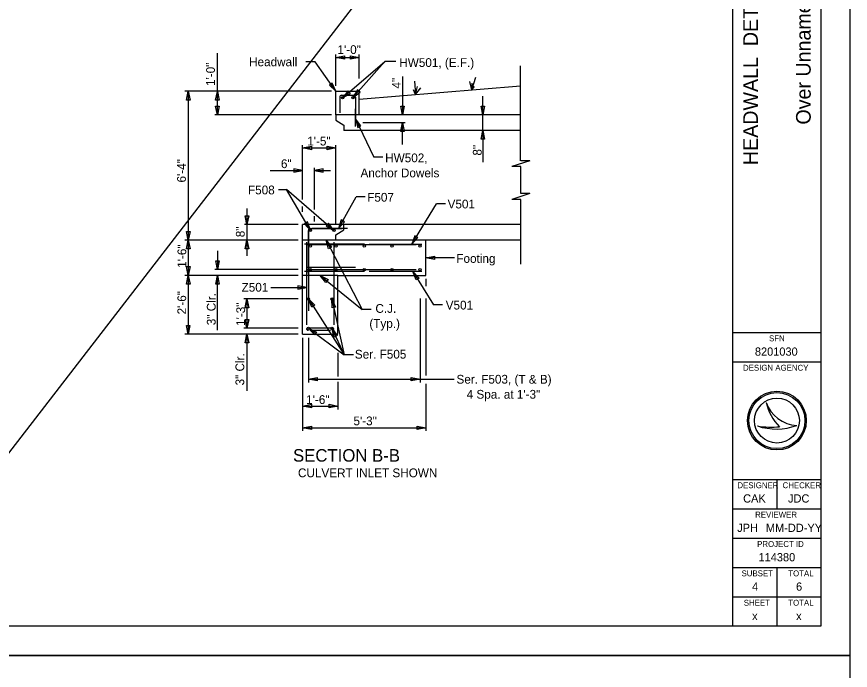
# Model space of a CAD drawing. Extents: x -1609 to 1184, y -412 to 394.
# Drawn here: x -1077.4 to -1041.89, y -99.47 to -71.66 of the extents above; entities that cross this region are included whole.
import ezdxf

# ---------------------------------------------------------------- set-up
doc = ezdxf.new("R2010")
doc.units = 0
for name, color, linetype in [('SH_Border', 7, 'Continuous'), ('SH_Cut_Line', 7, 'Continuous'), ('SH_Data', 7, 'Continuous'), ('ST_Details', 7, 'Continuous'), ('ST_Text', 7, 'Continuous'), ('XS_P_Finished_Grade', 7, 'Continuous')]:
    doc.layers.add(name, color=color, linetype=linetype)

msp = doc.modelspace()

# ---------------------------------------------------------------- linework, layer by layer
at = {"layer": 'SH_Border'}
for p, q in [((-1046.891, -97.594), (-1046.891, -45.094)), ((-1046.891, -85.094), (-1043.141, -85.094)), ((-1046.891, -86.344), (-1043.141, -86.344)), ((-1046.891, -91.344), (-1043.141, -91.344)), ((-1045.016, -91.344), (-1045.016, -92.594)), ((-1046.891, -92.594), (-1043.141, -92.594)), ((-1046.891, -93.844), (-1043.141, -93.844)), ((-1046.891, -95.094), (-1043.141, -95.094)), ((-1045.016, -95.094), (-1045.016, -96.344)), ((-1046.891, -96.344), (-1043.141, -96.344)), ((-1045.016, -96.344), (-1045.016, -97.594))]:
    msp.add_line(p, q, dxfattribs=at)
msp.add_lwpolyline([(-1123.141, -45.094), (-1043.141, -45.094), (-1043.141, -97.594), (-1123.141, -97.594)], close=True, dxfattribs=at)
at = {"layer": 'SH_Cut_Line'}
for points in [[(-1126.891, -98.844), (-1041.891, -98.844), (-1041.891, -43.844), (-1126.891, -43.844)], [(-1126.891, -153.844), (-1041.891, -153.844), (-1041.891, -98.844), (-1126.891, -98.844)]]:
    msp.add_lwpolyline(points, close=True, dxfattribs=at)
at = {"layer": 'SH_Data'}
for p, q in [((-1045.472, -88.07), (-1045.472, -88.07)), ((-1045.848, -89.07), (-1045.848, -89.07)), ((-1045.016, -88.844), (-1045.016, -88.844)), ((-1044.173, -89.048), (-1044.173, -89.048))]:
    msp.add_line(p, q, dxfattribs=at)
for radius in [1.25, 1.192, 1.192, 0.956]:
    msp.add_circle((-1045.016, -88.844), radius, dxfattribs=at)
for centre, radius, start, end in [((-1044.101, -87.6), 1.45, 198.9257, 198.9319), ((-1043.524, -87.669), 1.989, 191.6379, 191.6421), ((-1044.101, -87.6), 1.45, 198.9319, 267.1657), ((-1043.524, -87.669), 1.989, 191.6421, 226.0947), ((-1045.042, -86.669), 2.533, 251.4576, 290.0832), ((-1045.271, -85.958), 3.165, 259.4964, 259.4995), ((-1045.042, -86.669), 2.533, 251.4527, 251.4576), ((-1045.271, -85.958), 3.165, 259.4995, 276.6672)]:
    msp.add_arc(centre, radius, start, end, dxfattribs=at)
at = {"layer": 'ST_Details'}
for p, q in [((-1055.931, -77.783), (-1055.931, -73.749)), ((-1060.449, -74.396), (-1060.406, -74.965)), ((-1058.015, -74.766), (-1058.099, -74.408)), ((-1058.015, -74.766), (-1057.843, -74.23)), ((-1058.004, -74.486), (-1058.015, -74.766)), ((-1063.802, -75.832), (-1063.802, -74.832)), ((-1063.802, -74.832), (-1062.802, -74.832)), ((-1062.802, -75.832), (-1062.802, -74.832)), ((-1060.406, -74.965), (-1060.497, -74.771)), ((-1060.406, -74.965), (-1060.326, -74.62)), ((-1060.406, -74.965), (-1060.185, -74.681)), ((-1058.015, -74.766), (-1057.903, -74.622)), ((-1063.635, -75.079), (-1063.635, -75.748)), ((-1063.555, -74.999), (-1063.048, -74.999)), ((-1062.968, -75.079), (-1062.968, -76.165)), ((-1062.968, -76.332), (-1062.968, -75.578)), ((-1063.802, -75.832), (-1063.802, -75.836)), ((-1055.931, -75.832), (-1063.802, -75.832)), ((-1063.802, -75.832), (-1063.802, -76.054)), ((-1063.802, -76.054), (-1063.469, -76.276)), ((-1063.469, -76.276), (-1063.469, -76.498)), ((-1055.931, -76.499), (-1063.469, -76.499)), ((-1055.539, -77.783), (-1056.313, -78.028)), ((-1055.926, -78.028), (-1056.313, -78.028)), ((-1055.539, -77.783), (-1055.926, -77.783)), ((-1055.926, -79.186), (-1055.926, -78.028)), ((-1055.535, -79.186), (-1056.308, -79.431)), ((-1055.921, -79.431), (-1056.308, -79.431)), ((-1055.926, -82.19), (-1055.926, -79.431)), ((-1055.535, -79.186), (-1055.921, -79.186)), ((-1063.469, -80.499), (-1065.218, -80.499)), ((-1065.218, -81.499), (-1065.218, -80.499)), ((-1063.469, -80.721), (-1063.469, -80.499)), ((-1055.931, -80.499), (-1063.469, -80.499)), ((-1064.969, -80.745), (-1064.969, -84.169)), ((-1064.969, -82.582), (-1064.969, -80.749)), ((-1064.886, -80.665), (-1063.552, -80.665)), ((-1063.301, -80.665), (-1064.82, -80.665)), ((-1063.802, -80.943), (-1063.469, -80.721)), ((-1063.802, -81.165), (-1063.802, -80.943)), ((-1065.218, -85.165), (-1065.218, -81.165)), ((-1063.802, -81.165), (-1065.218, -81.165)), ((-1059.968, -81.165), (-1063.802, -81.165)), ((-1055.931, -81.165), (-1063.802, -81.165)), ((-1059.968, -82.665), (-1059.968, -81.165)), ((-1062.585, -81.332), (-1065.135, -81.332)), ((-1065.052, -81.344), (-1060.384, -81.344)), ((-1063.885, -81.333), (-1063.885, -83.836)), ((-1062.385, -81.332), (-1060.135, -81.332)), ((-1062.966, -82.332), (-1065.052, -82.332)), ((-1063.718, -82.665), (-1065.218, -82.665)), ((-1065.052, -82.419), (-1060.384, -82.419)), ((-1063.718, -82.665), (-1059.968, -82.665)), ((-1063.718, -85.165), (-1063.718, -82.665)), ((-1060.135, -82.499), (-1062.385, -82.499)), ((-1065.218, -85.165), (-1063.718, -85.165)), ((-1063.965, -84.915), (-1064.903, -84.915))]:
    msp.add_line(p, q, dxfattribs=at)
for points in [[(-1065.052, -81.249), (-1065.052, -84.769)], [(-1063.885, -81.249), (-1063.885, -83.583)], [(-1065.052, -81.344), (-1063.052, -81.344)], [(-1062.585, -82.499), (-1065.135, -82.499)], [(-1063.885, -83.453), (-1063.885, -84.769)], [(-1064.903, -84.999), (-1064.032, -84.999)]]:
    msp.add_lwpolyline(points, dxfattribs=at)
for centre in [(-1063.517, -75.105), (-1063.077, -75.097), (-1064.886, -80.749), (-1063.885, -80.749), (-1064.886, -81.415), (-1063.802, -81.415), (-1062.593, -81.415), (-1061.406, -81.415), (-1060.218, -81.415), (-1064.886, -82.416), (-1063.802, -82.416), (-1062.593, -82.415), (-1061.406, -82.415), (-1060.218, -82.415), (-1064.968, -83.666), (-1063.968, -83.666), (-1064.968, -84.916), (-1063.968, -84.916)]:
    msp.add_circle(centre, 0.0502, dxfattribs=at)
for centre, radius, start, end in [((-1063.555, -75.079), 0.08, 90, 180), ((-1063.048, -75.079), 0.08, 0, 90), ((-1064.886, -80.749), 0.0833, 90, 180), ((-1064.972, -84.919), 0.08, 180, 270), ((-1063.965, -84.919), 0.08, 270, 0)]:
    msp.add_arc(centre, radius, start, end, dxfattribs=at)
at = {"layer": 'ST_Text'}
for p, q in [((-1068.846, -74.839), (-1068.846, -73.211)), ((-1063.802, -74.604), (-1063.802, -73.26)), ((-1063.802, -73.392), (-1062.802, -73.392)), ((-1062.802, -74.293), (-1062.802, -73.26)), ((-1064.68, -73.579), (-1065.081, -73.579)), ((-1063.802, -74.832), (-1064.68, -73.579)), ((-1063.517, -75.105), (-1061.72, -73.563)), ((-1063.077, -75.097), (-1061.72, -73.563)), ((-1061.254, -73.563), (-1061.72, -73.563)), ((-1060.966, -74.205), (-1060.966, -75.832)), ((-1063.988, -74.832), (-1070.233, -74.832)), ((-1070.088, -74.832), (-1070.088, -81.165)), ((-1068.846, -75.832), (-1068.846, -74.832)), ((-1057.539, -75.832), (-1057.539, -75.039)), ((-1063.988, -75.832), (-1068.951, -75.832)), ((-1057.539, -76.499), (-1057.539, -75.832)), ((-1062.968, -75.999), (-1062.188, -77.639)), ((-1062.646, -76.165), (-1060.852, -76.165)), ((-1060.966, -77.096), (-1060.966, -76.165)), ((-1057.539, -76.499), (-1057.539, -77.85)), ((-1065.218, -79.435), (-1065.218, -77.122)), ((-1065.218, -77.243), (-1063.802, -77.243)), ((-1063.802, -80.499), (-1063.802, -77.122)), ((-1061.801, -77.639), (-1062.188, -77.639)), ((-1064.718, -79.859), (-1064.718, -78.087)), ((-1066.605, -78.201), (-1065.218, -78.201)), ((-1064.718, -78.201), (-1064.029, -78.201)), ((-1066.247, -79.011), (-1065.903, -79.011)), ((-1064.886, -80.749), (-1065.903, -79.011)), ((-1063.885, -80.749), (-1065.903, -79.011)), ((-1063.69, -80.665), (-1062.931, -79.327)), ((-1062.548, -79.327), (-1062.931, -79.327)), ((-1067.589, -79.815), (-1067.589, -80.499)), ((-1065.218, -79.954), (-1065.218, -79.734)), ((-1060.572, -81.332), (-1059.519, -79.617)), ((-1059.136, -79.617), (-1059.519, -79.617)), ((-1064.718, -80.367), (-1064.718, -80.151)), ((-1065.404, -80.499), (-1067.686, -80.499)), ((-1067.589, -80.491), (-1067.589, -81.165)), ((-1065.404, -81.165), (-1070.233, -81.165)), ((-1070.088, -81.165), (-1070.088, -82.665)), ((-1067.589, -81.165), (-1067.589, -81.839)), ((-1064.22, -81.165), (-1062.687, -84.115)), ((-1068.839, -81.618), (-1068.839, -82.415)), ((-1058.755, -81.915), (-1059.968, -81.915)), ((-1065.404, -82.665), (-1070.233, -82.665)), ((-1070.088, -82.665), (-1070.088, -83.408)), ((-1065.404, -82.415), (-1068.951, -82.415)), ((-1068.839, -84.998), (-1068.839, -82.665)), ((-1064.468, -82.665), (-1062.687, -84.115)), ((-1060.517, -82.499), (-1059.65, -83.912)), ((-1059.968, -82.809), (-1059.968, -83.13)), ((-1070.089, -83.408), (-1070.089, -85.165)), ((-1066.577, -83.182), (-1065.052, -83.182)), ((-1065.404, -83.666), (-1067.717, -83.666)), ((-1067.589, -83.666), (-1067.589, -84.916)), ((-1064.968, -83.666), (-1063.442, -86.04)), ((-1063.968, -83.666), (-1063.442, -86.04)), ((-1060.218, -83.641), (-1060.218, -87.226)), ((-1059.968, -83.641), (-1059.968, -86.929)), ((-1062.296, -84.115), (-1062.687, -84.115)), ((-1059.259, -83.912), (-1059.65, -83.912)), ((-1065.404, -85.165), (-1070.233, -85.165)), ((-1065.404, -84.916), (-1067.717, -84.916)), ((-1067.589, -85.165), (-1067.589, -87.583)), ((-1064.968, -84.916), (-1063.442, -86.04)), ((-1063.968, -84.916), (-1063.442, -86.04)), ((-1065.218, -85.326), (-1065.218, -89.275)), ((-1064.968, -85.326), (-1064.968, -87.226)), ((-1063.718, -85.959), (-1063.718, -86.97)), ((-1063.054, -86.04), (-1063.442, -86.04)), ((-1064.968, -87.081), (-1060.218, -87.081)), ((-1063.718, -87.193), (-1063.718, -88.374)), ((-1060.218, -87.081), (-1058.764, -87.081)), ((-1059.968, -87.278), (-1059.968, -89.275)), ((-1065.218, -88.225), (-1063.718, -88.225)), ((-1065.218, -89.149), (-1059.968, -89.149))]:
    msp.add_line(p, q, dxfattribs=at)
for points in [[(-1063.428, -73.466), (-1063.802, -73.392), (-1063.428, -73.317)], [(-1063.175, -73.317), (-1062.802, -73.392), (-1063.175, -73.466)], [(-1064.077, -74.569), (-1063.802, -74.832), (-1063.955, -74.484)], [(-1070.162, -75.205), (-1070.088, -74.832), (-1070.013, -75.205)], [(-1068.921, -75.213), (-1068.846, -74.839), (-1068.772, -75.213)], [(-1063.283, -74.805), (-1063.517, -75.105), (-1063.185, -74.918)], [(-1062.885, -74.768), (-1063.077, -75.097), (-1062.773, -74.867)], [(-1068.772, -75.458), (-1068.846, -75.832), (-1068.921, -75.458)], [(-1060.892, -75.458), (-1060.966, -75.832), (-1061.041, -75.458)], [(-1057.465, -75.458), (-1057.539, -75.832), (-1057.614, -75.458)], [(-1062.737, -76.301), (-1062.968, -75.999), (-1062.871, -76.367)], [(-1061.041, -76.539), (-1060.966, -76.165), (-1060.892, -76.539)], [(-1057.614, -76.872), (-1057.539, -76.499), (-1057.465, -76.872)], [(-1064.845, -77.317), (-1065.218, -77.243), (-1064.845, -77.168)], [(-1064.175, -77.168), (-1063.802, -77.243), (-1064.175, -77.317)], [(-1065.592, -78.276), (-1065.218, -78.201), (-1065.592, -78.127)], [(-1064.345, -78.127), (-1064.718, -78.201), (-1064.345, -78.276)], [(-1067.515, -80.125), (-1067.589, -80.499), (-1067.664, -80.125)], [(-1065.139, -80.464), (-1064.886, -80.749), (-1065.01, -80.389)], [(-1064.216, -80.561), (-1063.885, -80.749), (-1064.119, -80.448)], [(-1063.569, -80.304), (-1063.69, -80.665), (-1063.439, -80.379)], [(-1070.013, -80.792), (-1070.088, -81.165), (-1070.162, -80.792)], [(-1070.162, -81.539), (-1070.088, -81.165), (-1070.013, -81.539)], [(-1067.664, -81.539), (-1067.589, -81.165), (-1067.515, -81.539)], [(-1064.116, -81.532), (-1064.22, -81.165), (-1063.983, -81.463)], [(-1060.44, -80.975), (-1060.572, -81.332), (-1060.313, -81.053)], [(-1059.595, -81.99), (-1059.968, -81.915), (-1059.595, -81.841)], [(-1070.013, -82.292), (-1070.088, -82.665), (-1070.162, -82.292)], [(-1068.765, -82.042), (-1068.839, -82.415), (-1068.914, -82.042)], [(-1070.162, -83.039), (-1070.088, -82.665), (-1070.013, -83.039)], [(-1068.914, -83.039), (-1068.839, -82.665), (-1068.765, -83.039)], [(-1064.227, -82.96), (-1064.468, -82.665), (-1064.132, -82.844)], [(-1060.385, -82.856), (-1060.517, -82.499), (-1060.258, -82.778)], [(-1065.425, -83.257), (-1065.052, -83.182), (-1065.425, -83.107)], [(-1067.664, -84.039), (-1067.589, -83.666), (-1067.515, -84.039)], [(-1064.822, -84.017), (-1064.968, -83.666), (-1064.698, -83.934)], [(-1063.959, -84.046), (-1063.968, -83.666), (-1063.813, -84.013)], [(-1070.015, -84.792), (-1070.089, -85.165), (-1070.164, -84.792)], [(-1067.515, -84.542), (-1067.589, -84.916), (-1067.664, -84.542)], [(-1067.664, -85.539), (-1067.589, -85.165), (-1067.515, -85.539)], [(-1064.713, -85.198), (-1064.968, -84.916), (-1064.624, -85.078)], [(-1063.88, -85.286), (-1063.968, -84.916), (-1063.744, -85.223)], [(-1064.595, -87.155), (-1064.968, -87.081), (-1064.595, -87.006)], [(-1060.592, -87.006), (-1060.218, -87.081), (-1060.592, -87.155)], [(-1064.845, -88.3), (-1065.218, -88.225), (-1064.845, -88.15)], [(-1064.092, -88.15), (-1063.718, -88.225), (-1064.092, -88.3)], [(-1064.845, -89.224), (-1065.218, -89.149), (-1064.845, -89.075)], [(-1060.342, -89.075), (-1059.968, -89.149), (-1060.342, -89.224)]]:
    msp.add_lwpolyline(points, close=True, dxfattribs=at)
at = {"layer": 'XS_P_Finished_Grade'}
for p, q in [((-1126.891, -153.844), (-1041.891, -43.844)), ((-1062.802, -75.165), (-1055.931, -74.593))]:
    msp.add_line(p, q, dxfattribs=at)

# ---------------------------------------------------------------- texts
at = {"layer": 'SH_Data'}
for s, p in [('HEADWALL  DETAILS  FOR  CULVERT  OUTLET', (-1045.828, -77.972)), ('Over Unnamed Tributary of Brushy Creek', (-1043.578, -76.247))]:
    msp.add_text(s, height=0.625, rotation=90, dxfattribs=at).set_placement(p)
for s, height, p in [('SFN', 0.25, (-1045.351, -85.469)), ('8201030', 0.35, (-1045.955, -86.081)), ('DESIGN AGENCY', 0.25, (-1046.461, -86.719)), ('DESIGNER', 0.25, (-1046.699, -91.719)), ('CHECKER', 0.25, (-1044.776, -91.719)), ('CAK', 0.35, (-1046.456, -92.331)), ('JDC', 0.35, (-1044.544, -92.331)), ('REVIEWER', 0.25, (-1045.945, -92.969)), ('JPH', 0.35, (-1046.708, -93.581)), ('MM-DD-YY', 0.35, (-1045.487, -93.581)), ('PROJECT ID', 0.25, (-1045.859, -94.219)), ('114380', 0.35, (-1045.801, -94.831)), ('SUBSET', 0.25, (-1046.523, -95.469)), ('TOTAL', 0.25, (-1044.534, -95.469)), ('4', 0.35, (-1046.077, -96.081)), ('6', 0.35, (-1044.203, -96.081)), ('SHEET', 0.25, (-1046.428, -96.719)), ('TOTAL', 0.25, (-1044.534, -96.719)), ('x', 0.35, (-1046.074, -97.331)), ('x', 0.35, (-1044.199, -97.331))]:
    msp.add_text(s, height=height, dxfattribs=at).set_placement(p)
at = {"layer": 'ST_Text'}
for s, height, p in [('1\'-0"', 0.3733, (-1063.731, -73.244)), ('Headwall', 0.3733, (-1067.497, -73.765)), ('HW501, (E.F.)', 0.37335, (-1061.1, -73.795)), ('1\'-5"', 0.3733, (-1065.02, -77.137)), ('6"', 0.3733, (-1066.141, -78.099)), ('HW502,', 0.3733, (-1061.7, -77.851)), ('Anchor Dowels', 0.37335, (-1062.751, -78.491)), ('F508', 0.3733, (-1067.543, -79.216)), ('F507', 0.3733, (-1062.466, -79.528)), ('V501', 0.3733, (-1059.043, -79.815)), ('Footing', 0.3733, (-1058.669, -82.131)), ('Z501', 0.3733, (-1067.816, -83.357)), ('V501', 0.3733, (-1059.123, -84.116)), ('C.J.', 0.3733, (-1062.117, -84.258)), ('(Typ.)', 0.3733, (-1062.375, -84.898)), ('Ser. F505', 0.3733, (-1062.992, -86.205)), ('Ser. F503, (T & B)', 0.37335, (-1058.664, -87.271)), ('4 Spa. at 1\'-3"', 0.37335, (-1058.23, -87.911)), ('1\'-6"', 0.3733, (-1065.066, -88.136)), ('5\'-3"', 0.3733, (-1063.052, -89.044)), ('SECTION B-B', 0.53335, (-1065.626, -90.59)), ('CULVERT INLET SHOWN', 0.37335, (-1065.415, -91.253))]:
    msp.add_text(s, height=height, dxfattribs=at).set_placement(p)
for s, p in [('1\'-0"', (-1068.952, -74.605)), ('4"', (-1061.037, -74.714)), ('8"', (-1057.593, -77.567)), ('6\'-4"', (-1070.19, -78.711)), ('8"', (-1067.685, -81.041)), ('1\'-6"', (-1070.172, -82.342)), ('2\'-6"', (-1070.178, -84.325)), ('3" Clr.', (-1068.921, -84.786)), ('1\'-3"', (-1067.668, -84.816)), ('3" Clr.', (-1067.703, -87.347))]:
    msp.add_text(s, height=0.3733, rotation=90, dxfattribs=at).set_placement(p)

doc.saveas('drawing.dxf')
